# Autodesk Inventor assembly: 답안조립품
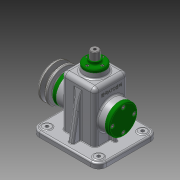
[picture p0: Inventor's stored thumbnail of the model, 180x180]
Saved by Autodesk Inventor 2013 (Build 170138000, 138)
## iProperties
Created: 2016-01
Part Number: 답안조립품
Document SubType Name: Assembly
Designer: User
Author: User
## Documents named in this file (19)
- C:\Users\User\Desktop\460126V1014\답안조립품.iam
- C:\Users\User\Desktop\460126V1014\본체.ipt
- C:\Users\User\Desktop\460126V1014\뒤커버.ipt
- C:\Users\User\Desktop\460126V1014\앞커버.ipt
- C:\Users\User\Desktop\460126V1014\상부부시.ipt
- C:\Users\User\Desktop\460126V1014\베어링 15 x 35 x 11.ipt
- C:\Users\User\Desktop\460126V1014\오일실 15 25 7.ipt
- C:\Users\User\Desktop\460126V1014\편심축.ipt
- C:\Users\User\Desktop\460126V1014\키 5 x 5 x 14.ipt
- C:\Users\User\Desktop\460126V1014\멈춤링 15 x 1.ipt
- C:\Users\User\Desktop\460126V1014\V-벨트풀리.ipt
- C:\Users\User\Desktop\460126V1014\볼트 M6 x 12.ipt
- C:\Users\User\Desktop\460126V1014\와셔.ipt
- C:\Users\User\Desktop\460126V1014\링크.ipt
- C:\Users\User\Desktop\460126V1014\멈춤링 6 x 5.ipt
- C:\Users\User\Desktop\460126V1014\고정핀.ipt
- C:\Users\User\Desktop\460126V1014\슬라이드바.ipt
- C:\Users\User\Desktop\460126V1014\볼트 M3 x 8.ipt
- C:\Users\User\Desktop\460126V1014\볼트 M4 x 10.ipt
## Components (15 placed, 5 different names)
1. V-벨트풀리:1
2. ISO 4018 M6 x 12:1
3. 고정핀:1
4. ISO 4762 M3 x 8:1
5. ISO 4762 M3 x 8:2
6. ISO 4762 M3 x 8:3
7. ISO 4762 M3 x 8:4
8. ISO 4762 M4 x 10:1
9. ISO 4762 M4 x 10:2
10. ISO 4762 M4 x 10:3
11. ISO 4762 M4 x 10:4
12. ISO 4762 M4 x 10:5
13. ISO 4762 M4 x 10:6
14. ISO 4762 M4 x 10:7
15. ISO 4762 M4 x 10:8
